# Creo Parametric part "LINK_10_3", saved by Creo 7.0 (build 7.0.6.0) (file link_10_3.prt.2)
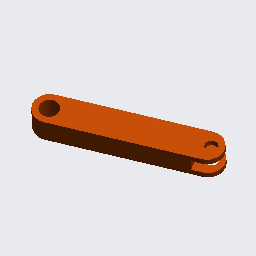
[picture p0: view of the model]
Units: millimeter Newton Second (mmNs); MM, TONNE, SECS

Created from: XX_MMNS_PART_SOLID_ABS.PRT

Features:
  1. datum plane "RIGHT"
  2. datum plane "TOP"
  3. datum plane "FRONT"
  4. coordinate system
  5. extrusion "Extrude 1"
  6. extruded cut "Extrude 2"
  7. extruded cut "Extrude 3"
  8. extruded cut "Extrude 4"

Surfaces: 7 plane, 4 cylinder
